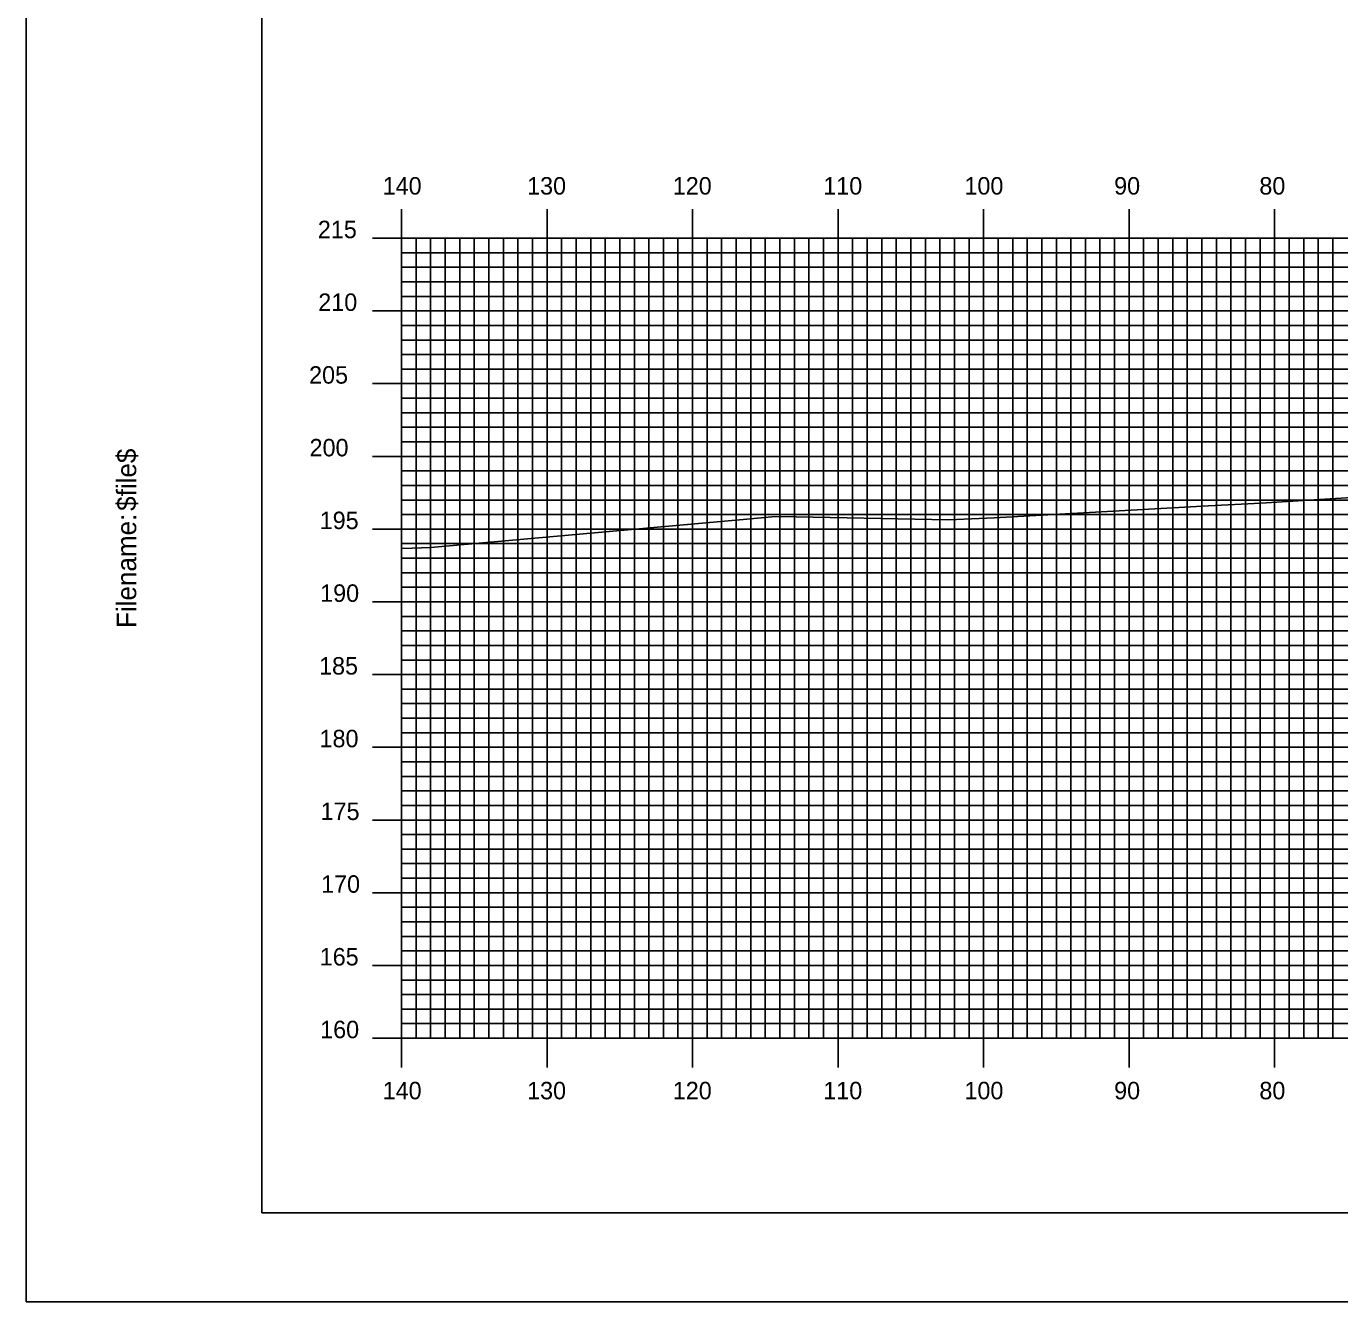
# Model space of a CAD drawing. Extents: x 1795240 to 1795583, y 442591 to 442811.
# Drawn here: x 1795239.6 to 1795329.8, y 442590.5 to 442678.2 of the extents above; entities that cross this region are included whole.
import ezdxf

# ---------------------------------------------------------------- set-up
doc = ezdxf.new("R2010")
doc.units = 0
for name, color, linetype in [('BORDER', 7, 'Continuous'), ('H_V ANNOTATION', 7, 'Continuous'), ('MAJOR', 7, 'Continuous'), ('MINOR', 7, 'Continuous'), ('PLOT BOUNDARY', 7, 'Continuous'), ('S_Roadway_Centerline', 7, 'Continuous')]:
    doc.layers.add(name, color=color, linetype=linetype)

msp = doc.modelspace()

# ---------------------------------------------------------------- linework, layer by layer
at = {"layer": 'BORDER'}
msp.add_lwpolyline([(1795255.766, 442596.665), (1795575.766, 442596.665), (1795575.766, 442806.665), (1795255.766, 442806.665)], close=True, dxfattribs=at)
at = {"layer": 'MAJOR'}
for p, q in [((1795265.366, 442665.669), (1795265.366, 442663.665)), ((1795275.366, 442665.669), (1795275.366, 442663.665)), ((1795285.366, 442665.669), (1795285.366, 442663.665)), ((1795295.366, 442665.669), (1795295.366, 442663.665)), ((1795305.366, 442665.669), (1795305.366, 442663.665)), ((1795315.366, 442665.669), (1795315.366, 442663.665)), ((1795325.366, 442665.669), (1795325.366, 442663.665)), ((1795263.362, 442663.665), (1795265.366, 442663.665)), ((1795265.366, 442663.665), (1795545.366, 442663.665)), ((1795265.366, 442608.665), (1795265.366, 442663.665)), ((1795265.366, 442608.665), (1795265.366, 442663.665)), ((1795265.366, 442663.665), (1795545.366, 442663.665)), ((1795275.366, 442608.665), (1795275.366, 442663.665)), ((1795285.366, 442608.665), (1795285.366, 442663.665)), ((1795295.366, 442608.665), (1795295.366, 442663.665)), ((1795305.366, 442608.665), (1795305.366, 442663.665)), ((1795315.366, 442608.665), (1795315.366, 442663.665)), ((1795325.366, 442608.665), (1795325.366, 442663.665)), ((1795263.362, 442658.665), (1795265.366, 442658.665)), ((1795265.366, 442658.665), (1795545.366, 442658.665)), ((1795263.362, 442653.665), (1795265.366, 442653.665)), ((1795265.366, 442653.665), (1795545.366, 442653.665)), ((1795263.362, 442648.665), (1795265.366, 442648.665)), ((1795265.366, 442648.665), (1795545.366, 442648.665)), ((1795263.362, 442643.665), (1795265.366, 442643.665)), ((1795265.366, 442643.665), (1795545.366, 442643.665)), ((1795263.362, 442638.665), (1795265.366, 442638.665)), ((1795265.366, 442638.665), (1795545.366, 442638.665)), ((1795263.362, 442633.665), (1795265.366, 442633.665)), ((1795265.366, 442633.665), (1795545.366, 442633.665)), ((1795263.362, 442628.665), (1795265.366, 442628.665)), ((1795265.366, 442628.665), (1795545.366, 442628.665)), ((1795263.362, 442623.665), (1795265.366, 442623.665)), ((1795265.366, 442623.665), (1795545.366, 442623.665)), ((1795263.362, 442618.665), (1795265.366, 442618.665)), ((1795265.366, 442618.665), (1795545.366, 442618.665)), ((1795263.362, 442613.665), (1795265.366, 442613.665)), ((1795265.366, 442613.665), (1795545.366, 442613.665)), ((1795263.362, 442608.665), (1795265.366, 442608.665)), ((1795265.366, 442608.665), (1795545.366, 442608.665)), ((1795265.366, 442608.665), (1795545.366, 442608.665)), ((1795265.366, 442606.661), (1795265.366, 442608.665)), ((1795275.366, 442606.661), (1795275.366, 442608.665)), ((1795285.366, 442606.661), (1795285.366, 442608.665)), ((1795295.366, 442606.661), (1795295.366, 442608.665)), ((1795305.366, 442606.661), (1795305.366, 442608.665)), ((1795315.366, 442606.661), (1795315.366, 442608.665)), ((1795325.366, 442606.661), (1795325.366, 442608.665))]:
    msp.add_line(p, q, dxfattribs=at)
at = {"layer": 'MINOR'}
for p, q in [((1795266.366, 442608.665), (1795266.366, 442663.665)), ((1795267.366, 442608.665), (1795267.366, 442663.665)), ((1795268.366, 442608.665), (1795268.366, 442663.665)), ((1795269.366, 442608.665), (1795269.366, 442663.665)), ((1795270.366, 442608.665), (1795270.366, 442663.665)), ((1795271.366, 442608.665), (1795271.366, 442663.665)), ((1795272.366, 442608.665), (1795272.366, 442663.665)), ((1795273.366, 442608.665), (1795273.366, 442663.665)), ((1795274.366, 442608.665), (1795274.366, 442663.665)), ((1795276.366, 442608.665), (1795276.366, 442663.665)), ((1795277.366, 442608.665), (1795277.366, 442663.665)), ((1795278.366, 442608.665), (1795278.366, 442663.665)), ((1795279.366, 442608.665), (1795279.366, 442663.665)), ((1795280.366, 442608.665), (1795280.366, 442663.665)), ((1795281.366, 442608.665), (1795281.366, 442663.665)), ((1795282.366, 442608.665), (1795282.366, 442663.665)), ((1795283.366, 442608.665), (1795283.366, 442663.665)), ((1795284.366, 442608.665), (1795284.366, 442663.665)), ((1795286.366, 442608.665), (1795286.366, 442663.665)), ((1795287.366, 442608.665), (1795287.366, 442663.665)), ((1795288.366, 442608.665), (1795288.366, 442663.665)), ((1795289.366, 442608.665), (1795289.366, 442663.665)), ((1795290.366, 442608.665), (1795290.366, 442663.665)), ((1795291.366, 442608.665), (1795291.366, 442663.665)), ((1795292.366, 442608.665), (1795292.366, 442663.665)), ((1795293.366, 442608.665), (1795293.366, 442663.665)), ((1795294.366, 442608.665), (1795294.366, 442663.665)), ((1795296.366, 442608.665), (1795296.366, 442663.665)), ((1795297.366, 442608.665), (1795297.366, 442663.665)), ((1795298.366, 442608.665), (1795298.366, 442663.665)), ((1795299.366, 442608.665), (1795299.366, 442663.665)), ((1795300.366, 442608.665), (1795300.366, 442663.665)), ((1795301.366, 442608.665), (1795301.366, 442663.665)), ((1795302.366, 442608.665), (1795302.366, 442663.665)), ((1795303.366, 442608.665), (1795303.366, 442663.665)), ((1795304.366, 442608.665), (1795304.366, 442663.665)), ((1795306.366, 442608.665), (1795306.366, 442663.665)), ((1795307.366, 442608.665), (1795307.366, 442663.665)), ((1795308.366, 442608.665), (1795308.366, 442663.665)), ((1795309.366, 442608.665), (1795309.366, 442663.665)), ((1795310.366, 442608.665), (1795310.366, 442663.665)), ((1795311.366, 442608.665), (1795311.366, 442663.665)), ((1795312.366, 442608.665), (1795312.366, 442663.665)), ((1795313.366, 442608.665), (1795313.366, 442663.665)), ((1795314.366, 442608.665), (1795314.366, 442663.665)), ((1795316.366, 442608.665), (1795316.366, 442663.665)), ((1795317.366, 442608.665), (1795317.366, 442663.665)), ((1795318.366, 442608.665), (1795318.366, 442663.665)), ((1795319.366, 442608.665), (1795319.366, 442663.665)), ((1795320.366, 442608.665), (1795320.366, 442663.665)), ((1795321.366, 442608.665), (1795321.366, 442663.665)), ((1795322.366, 442608.665), (1795322.366, 442663.665)), ((1795323.366, 442608.665), (1795323.366, 442663.665)), ((1795324.366, 442608.665), (1795324.366, 442663.665)), ((1795326.366, 442608.665), (1795326.366, 442663.665)), ((1795327.366, 442608.665), (1795327.366, 442663.665)), ((1795328.366, 442608.665), (1795328.366, 442663.665)), ((1795329.366, 442608.665), (1795329.366, 442663.665)), ((1795265.366, 442662.665), (1795545.366, 442662.665)), ((1795265.366, 442662.665), (1795267.37, 442662.665)), ((1795265.366, 442661.665), (1795545.366, 442661.665)), ((1795265.366, 442661.665), (1795267.37, 442661.665)), ((1795265.366, 442660.665), (1795545.366, 442660.665)), ((1795265.366, 442660.665), (1795267.37, 442660.665)), ((1795265.366, 442659.665), (1795545.366, 442659.665)), ((1795265.366, 442659.665), (1795267.37, 442659.665)), ((1795265.366, 442657.665), (1795545.366, 442657.665)), ((1795265.366, 442657.665), (1795267.37, 442657.665)), ((1795265.366, 442656.665), (1795545.366, 442656.665)), ((1795265.366, 442656.665), (1795267.37, 442656.665)), ((1795265.366, 442655.665), (1795545.366, 442655.665)), ((1795265.366, 442655.665), (1795267.37, 442655.665)), ((1795265.366, 442654.665), (1795545.366, 442654.665)), ((1795265.366, 442654.665), (1795267.37, 442654.665)), ((1795265.366, 442652.665), (1795545.366, 442652.665)), ((1795265.366, 442652.665), (1795267.37, 442652.665)), ((1795265.366, 442651.665), (1795545.366, 442651.665)), ((1795265.366, 442651.665), (1795267.37, 442651.665)), ((1795265.366, 442650.665), (1795545.366, 442650.665)), ((1795265.366, 442650.665), (1795267.37, 442650.665)), ((1795265.366, 442649.665), (1795545.366, 442649.665)), ((1795265.366, 442649.665), (1795267.37, 442649.665)), ((1795265.366, 442647.665), (1795545.366, 442647.665)), ((1795265.366, 442647.665), (1795267.37, 442647.665)), ((1795265.366, 442646.665), (1795545.366, 442646.665)), ((1795265.366, 442646.665), (1795267.37, 442646.665)), ((1795265.366, 442645.665), (1795545.366, 442645.665)), ((1795265.366, 442645.665), (1795267.37, 442645.665)), ((1795265.366, 442644.665), (1795545.366, 442644.665)), ((1795265.366, 442644.665), (1795267.37, 442644.665)), ((1795265.366, 442642.665), (1795545.366, 442642.665)), ((1795265.366, 442642.665), (1795267.37, 442642.665)), ((1795265.366, 442641.665), (1795545.366, 442641.665)), ((1795265.366, 442641.665), (1795267.37, 442641.665)), ((1795265.366, 442640.665), (1795545.366, 442640.665)), ((1795265.366, 442640.665), (1795267.37, 442640.665)), ((1795265.366, 442639.665), (1795545.366, 442639.665)), ((1795265.366, 442639.665), (1795267.37, 442639.665)), ((1795265.366, 442637.665), (1795545.366, 442637.665)), ((1795265.366, 442637.665), (1795267.37, 442637.665)), ((1795265.366, 442636.665), (1795545.366, 442636.665)), ((1795265.366, 442636.665), (1795267.37, 442636.665)), ((1795265.366, 442635.665), (1795545.366, 442635.665)), ((1795265.366, 442635.665), (1795267.37, 442635.665)), ((1795265.366, 442634.665), (1795545.366, 442634.665)), ((1795265.366, 442634.665), (1795267.37, 442634.665)), ((1795265.366, 442632.665), (1795545.366, 442632.665)), ((1795265.366, 442632.665), (1795267.37, 442632.665)), ((1795265.366, 442631.665), (1795545.366, 442631.665)), ((1795265.366, 442631.665), (1795267.37, 442631.665)), ((1795265.366, 442630.665), (1795545.366, 442630.665)), ((1795265.366, 442630.665), (1795267.37, 442630.665)), ((1795265.366, 442629.665), (1795545.366, 442629.665)), ((1795265.366, 442629.665), (1795267.37, 442629.665)), ((1795265.366, 442627.665), (1795545.366, 442627.665)), ((1795265.366, 442627.665), (1795267.37, 442627.665)), ((1795265.366, 442626.665), (1795545.366, 442626.665)), ((1795265.366, 442626.665), (1795267.37, 442626.665)), ((1795265.366, 442625.665), (1795545.366, 442625.665)), ((1795265.366, 442625.665), (1795267.37, 442625.665)), ((1795265.366, 442624.665), (1795545.366, 442624.665)), ((1795265.366, 442624.665), (1795267.37, 442624.665)), ((1795265.366, 442622.665), (1795545.366, 442622.665)), ((1795265.366, 442622.665), (1795267.37, 442622.665)), ((1795265.366, 442621.665), (1795545.366, 442621.665)), ((1795265.366, 442621.665), (1795267.37, 442621.665)), ((1795265.366, 442620.665), (1795545.366, 442620.665)), ((1795265.366, 442620.665), (1795267.37, 442620.665)), ((1795265.366, 442619.665), (1795545.366, 442619.665)), ((1795265.366, 442619.665), (1795267.37, 442619.665)), ((1795265.366, 442617.665), (1795545.366, 442617.665)), ((1795265.366, 442617.665), (1795267.37, 442617.665)), ((1795265.366, 442616.665), (1795545.366, 442616.665)), ((1795265.366, 442616.665), (1795267.37, 442616.665)), ((1795265.366, 442615.665), (1795545.366, 442615.665)), ((1795265.366, 442615.665), (1795267.37, 442615.665)), ((1795265.366, 442614.665), (1795545.366, 442614.665)), ((1795265.366, 442614.665), (1795267.37, 442614.665)), ((1795265.366, 442612.665), (1795545.366, 442612.665)), ((1795265.366, 442612.665), (1795267.37, 442612.665)), ((1795265.366, 442611.665), (1795545.366, 442611.665)), ((1795265.366, 442611.665), (1795267.37, 442611.665)), ((1795265.366, 442610.665), (1795545.366, 442610.665)), ((1795265.366, 442610.665), (1795267.37, 442610.665)), ((1795265.366, 442609.665), (1795545.366, 442609.665)), ((1795265.366, 442609.665), (1795267.37, 442609.665))]:
    msp.add_line(p, q, dxfattribs=at)
at = {"layer": 'PLOT BOUNDARY'}
msp.add_lwpolyline([(1795239.579, 442590.547), (1795579.579, 442590.547), (1795579.579, 442810.547), (1795239.579, 442810.547)], close=True, dxfattribs=at)
at = {"layer": 'S_Roadway_Centerline'}
msp.add_lwpolyline([(1795265.366, 442642.34), (1795266.103, 442642.361), (1795267.377, 442642.389), (1795289.098, 442644.357), (1795290.825, 442644.5), (1795291.313, 442644.52), (1795302.97, 442644.294), (1795306.082, 442644.446), (1795320.826, 442645.256), (1795324.428, 442645.452), (1795326.992, 442645.604), (1795343.545, 442646.643)], dxfattribs=at)

# ---------------------------------------------------------------- texts
at = {"layer": 'BORDER'}
for s, p in [('$file$', (1795247.136, 442644.916)), ('Filename:', (1795247.136, 442636.862))]:
    msp.add_text(s, height=1.3392, rotation=90, dxfattribs=at).set_placement(p)
at = {"layer": 'H_V ANNOTATION'}
for s, p in [('140', (1795264.071, 442666.665)), ('130', (1795273.996, 442666.665)), ('120', (1795284.007, 442666.665)), ('110', (1795294.349, 442666.665)), ('100', (1795304.049, 442666.665)), ('90', (1795314.338, 442666.665)), ('80', (1795324.317, 442666.665)), ('215', (1795259.615, 442663.665)), ('210', (1795259.647, 442658.665)), ('205', (1795259.015, 442653.665)), ('200', (1795259.047, 442648.665)), ('195', (1795259.744, 442643.665)), ('190', (1795259.776, 442638.665)), ('185', (1795259.701, 442633.665)), ('180', (1795259.733, 442628.665)), ('175', (1795259.807, 442623.665)), ('170', (1795259.839, 442618.665)), ('165', (1795259.744, 442613.665)), ('160', (1795259.776, 442608.665)), ('140', (1795264.071, 442604.465)), ('130', (1795273.996, 442604.465)), ('120', (1795284.007, 442604.465)), ('110', (1795294.349, 442604.465)), ('100', (1795304.049, 442604.465)), ('90', (1795314.338, 442604.465)), ('80', (1795324.317, 442604.465))]:
    msp.add_text(s, height=1.2, dxfattribs=at).set_placement(p)
at = {"layer": 'MAJOR'}
msp.add_text('-', height=0.012, dxfattribs=at).set_placement((1795265.357, 442608.665))

doc.saveas('drawing.dxf')
